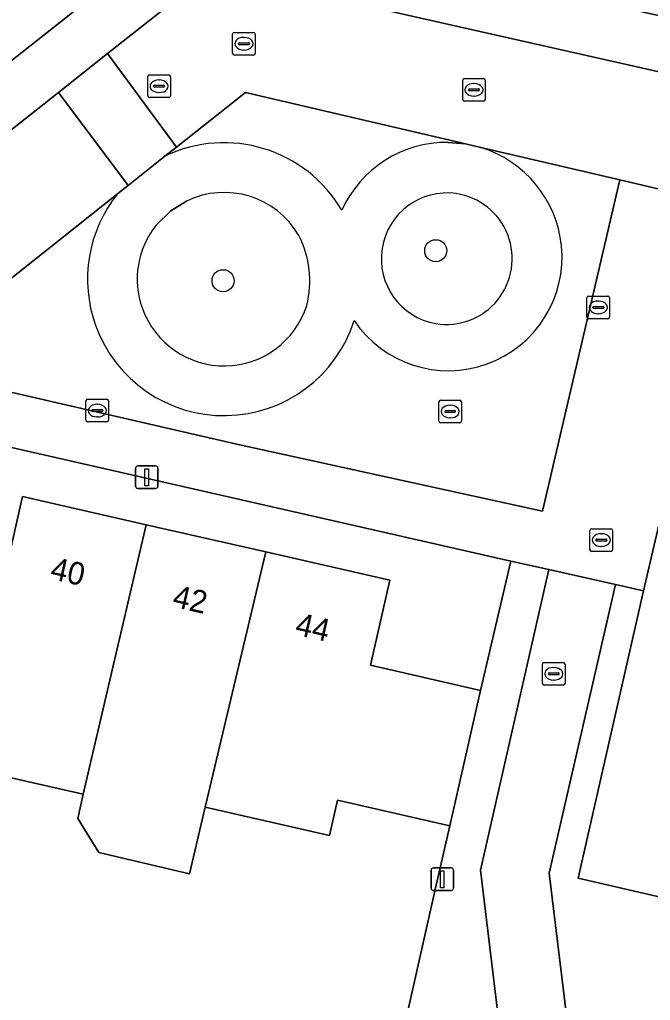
# Model space of a CAD drawing. Extents: x 159626 to 160723, y 388173 to 389416.
# Drawn here: x 160184.07 to 160211.96, y 388620.71 to 388664.1 of the extents above; entities that cross this region are included whole.
import ezdxf

# ---------------------------------------------------------------- set-up
doc = ezdxf.new("R2010")
doc.units = 0
for name, color, linetype in [('IMGEO_Boom', 7, 'Continuous'), ('IMGEO_Erf', 7, 'Continuous'), ('IMGEO_Groenvoorziening', 7, 'Continuous'), ('IMGEO_Kolk', 7, 'Continuous'), ('IMGEO_Lichtmast', 7, 'Continuous'), ('IMGEO_Muur', 7, 'Continuous'), ('IMGEO_Pand', 7, 'Continuous'), ('IMGEO_Pand_nummerreeks', 7, 'Continuous'), ('IMGEO_Rijbaan_lokaal_open', 7, 'Continuous'), ('IMGEO_Rioolput', 7, 'Continuous'), ('IMGEO_Voetpad_open', 7, 'Continuous')]:
    doc.layers.add(name, color=color, linetype=linetype)

msp = doc.modelspace()

# ---------------------------------------------------------------- linework, layer by layer
at = {"layer": 'IMGEO_Boom'}
for centre in [(160202.473, 388653.872), (160193.068, 388652.544)]:
    msp.add_circle(centre, 0.489, dxfattribs=at)
at = {"layer": 'IMGEO_Erf'}
for points in [[(160129.548, 388619.513), (160148.891, 388634.816), (160151.458, 388636.871), (160173.259, 388654.04), (160191.992, 388668.837), (160209.49, 388664.912), (160214.412, 388663.806), (160216.868, 388674.586), (160223.367, 388703.114)], [(160306.653, 388632.407), (160279.35, 388638.697), (160215.058, 388653.423), (160211.658, 388638.822), (160208.772, 388626.116), (160214.517, 388624.788), (160228.678, 388621.514), (160230.042, 388627.517), (160233.186, 388626.802), (160236.262, 388626.104), (160240.177, 388625.214), (160239.503, 388622.316), (160241.847, 388621.771), (160241.13, 388618.685)], [(160183.217, 388638.676), (160184.197, 388642.995), (160189.672, 388641.749), (160194.954, 388640.547), (160200.446, 388639.297), (160199.578, 388635.543), (160204.449, 388634.417), (160205.792, 388640.146), (160179.424, 388646.134)], [(160203.092, 388628.438), (160198.119, 388629.567), (160197.765, 388628.007), (160192.28, 388629.252), (160191.582, 388626.303), (160187.575, 388627.251), (160186.639, 388628.758), (160186.882, 388629.828), (160181.471, 388631.056)], [(160182.93, 388618.85), (160187.218, 388613.557), (160189.07, 388615.1), (160191.07, 388612.62), (160197.39, 388617.71), (160199.266, 388617.167), (160200.816, 388618.41), (160202.45, 388625.61), (160203.092, 388628.438)]]:
    msp.add_lwpolyline(points, dxfattribs=at)
at = {"layer": 'IMGEO_Groenvoorziening'}
for points in [[(160204.458, 388658.44), (160203.78, 388658.598), (160203.02, 388658.663)], [(160190.491, 388658.053), (160188.864, 388656.76), (160188.397, 388656.388)], [(160190.112, 388655.01), (160190.749, 388655.637), (160191.445, 388656.071)], [(160191.445, 388656.071), (160190.749, 388655.637), (160190.112, 388655.01)]]:
    msp.add_lwpolyline(points, dxfattribs=at)
for centre, radius, start, end in [((160193.107, 388652.616), 6.034, 30.3106, 115.694), ((160202.963, 388653.566), 5.098, 89.3598, 155.7306), ((160202.96, 388653.568), 5.097, 5.9014, 72.9066), ((160193.086, 388652.619), 6.016, 141.2048, 199.8162), ((160193.107, 388652.614), 3.835, 30.3293, 115.6727), ((160193.107, 388652.614), 3.835, 30.3293, 115.6727), ((160202.978, 388653.517), 2.914, 82.0671, 260.1206), ((160202.978, 388653.517), 2.914, 82.0671, 260.1206), ((160202.94, 388653.523), 2.913, 260.8691, 81.3185), ((160202.94, 388653.523), 2.913, 260.8691, 81.3185), ((160193.087, 388652.618), 3.818, 141.2063, 199.864), ((160193.087, 388652.618), 3.818, 141.2063, 199.864), ((160192.463, 388652.532), 4.439, 345.8967, 27.0554), ((160192.463, 388652.532), 4.439, 345.8967, 27.0554), ((160203.032, 388653.587), 5.023, 213.9515, 5.7746), ((160193.111, 388652.617), 3.839, 199.7252, 342.3074), ((160193.111, 388652.617), 3.839, 199.7252, 342.3074), ((160193.111, 388652.616), 6.039, 199.7158, 342.3075)]:
    msp.add_arc(centre, radius, start, end, dxfattribs=at)
at = {"layer": 'IMGEO_Kolk'}
for p, q in [((160189.735, 388660.724), (160189.735, 388661.576)), ((160189.81, 388661.65), (160190.662, 388661.65)), ((160190.736, 388661.576), (160190.736, 388660.724)), ((160189.994, 388661.144), (160189.994, 388661.156)), ((160190.432, 388661.107), (160190.034, 388661.107)), ((160190.037, 388661.193), (160190.435, 388661.193)), ((160190.223, 388661.43), (160190.248, 388661.43)), ((160190.478, 388661.156), (160190.478, 388661.144)), ((160203.661, 388660.565), (160203.661, 388661.417)), ((160203.736, 388661.491), (160204.588, 388661.491)), ((160204.149, 388661.271), (160204.174, 388661.271)), ((160204.662, 388661.417), (160204.662, 388660.565)), ((160190.246, 388660.87), (160190.221, 388660.87)), ((160203.92, 388660.985), (160203.92, 388660.997)), ((160204.358, 388660.948), (160203.96, 388660.948)), ((160203.963, 388661.034), (160204.361, 388661.034)), ((160204.172, 388660.711), (160204.147, 388660.711)), ((160204.404, 388660.997), (160204.404, 388660.985)), ((160190.662, 388660.65), (160189.81, 388660.65)), ((160204.588, 388660.491), (160203.736, 388660.491)), ((160209.158, 388650.938), (160209.158, 388651.79)), ((160209.233, 388651.864), (160210.085, 388651.864)), ((160209.646, 388651.644), (160209.671, 388651.644)), ((160210.159, 388651.79), (160210.159, 388650.938)), ((160209.417, 388651.358), (160209.417, 388651.37)), ((160209.855, 388651.321), (160209.457, 388651.321)), ((160209.46, 388651.407), (160209.858, 388651.407)), ((160209.901, 388651.37), (160209.901, 388651.358)), ((160210.085, 388650.864), (160209.233, 388650.864)), ((160209.669, 388651.084), (160209.644, 388651.084)), ((160187.002, 388646.376), (160187.002, 388647.228)), ((160187.077, 388647.302), (160187.929, 388647.302)), ((160188.003, 388647.228), (160188.003, 388646.376)), ((160202.682, 388647.259), (160203.534, 388647.259)), ((160187.261, 388646.796), (160187.261, 388646.808)), ((160187.304, 388646.845), (160187.702, 388646.845)), ((160187.49, 388647.082), (160187.515, 388647.082)), ((160187.745, 388646.808), (160187.745, 388646.796)), ((160202.607, 388646.333), (160202.607, 388647.185)), ((160202.909, 388646.802), (160203.307, 388646.802)), ((160203.095, 388647.039), (160203.12, 388647.039)), ((160203.608, 388647.185), (160203.608, 388646.333)), ((160187.699, 388646.759), (160187.301, 388646.759)), ((160187.513, 388646.522), (160187.488, 388646.522)), ((160202.866, 388646.753), (160202.866, 388646.765)), ((160203.304, 388646.716), (160202.906, 388646.716)), ((160203.118, 388646.479), (160203.093, 388646.479)), ((160203.35, 388646.765), (160203.35, 388646.753)), ((160187.929, 388646.302), (160187.077, 388646.302)), ((160203.534, 388646.259), (160202.682, 388646.259)), ((160207.19, 388634.73), (160207.19, 388635.582)), ((160207.265, 388635.656), (160208.117, 388635.656)), ((160208.191, 388635.582), (160208.191, 388634.73)), ((160207.449, 388635.15), (160207.449, 388635.162)), ((160207.887, 388635.113), (160207.489, 388635.113)), ((160207.492, 388635.199), (160207.89, 388635.199)), ((160207.678, 388635.436), (160207.703, 388635.436)), ((160207.933, 388635.162), (160207.933, 388635.15)), ((160208.117, 388634.656), (160207.265, 388634.656)), ((160207.701, 388634.876), (160207.676, 388634.876))]:
    msp.add_line(p, q, dxfattribs=at)
for points in [[(160189.735, 388660.724), (160189.735, 388661.576)], [(160189.81, 388661.65), (160190.662, 388661.65)], [(160190.736, 388661.576), (160190.736, 388660.724)], [(160203.661, 388660.565), (160203.661, 388661.417)], [(160203.736, 388661.491), (160204.588, 388661.491)], [(160204.662, 388661.417), (160204.662, 388660.565)], [(160190.662, 388660.65), (160189.81, 388660.65)], [(160204.588, 388660.491), (160203.736, 388660.491)], [(160209.158, 388650.938), (160209.158, 388651.79)], [(160209.233, 388651.864), (160210.085, 388651.864)], [(160210.159, 388651.79), (160210.159, 388650.938)], [(160210.085, 388650.864), (160209.233, 388650.864)], [(160187.002, 388646.376), (160187.002, 388647.228)], [(160187.077, 388647.302), (160187.929, 388647.302)], [(160188.003, 388647.228), (160188.003, 388646.376)], [(160202.682, 388647.259), (160203.534, 388647.259)], [(160202.607, 388646.333), (160202.607, 388647.185)], [(160203.608, 388647.185), (160203.608, 388646.333)], [(160187.929, 388646.302), (160187.077, 388646.302)], [(160203.534, 388646.259), (160202.682, 388646.259)], [(160207.19, 388634.73), (160207.19, 388635.582)], [(160207.265, 388635.656), (160208.117, 388635.656)], [(160208.191, 388635.582), (160208.191, 388634.73)], [(160208.117, 388634.656), (160207.265, 388634.656)]]:
    msp.add_lwpolyline(points, dxfattribs=at)
for centre, radius, start, end in [((160189.812, 388661.574), 0.0765, 91.552, 178.448), ((160189.812, 388661.574), 0.0765, 91.552, 178.448), ((160190.66, 388661.574), 0.0765, 1.552, 88.448), ((160190.66, 388661.574), 0.0765, 1.552, 88.448), ((160190.034, 388661.153), 0.0403, 85.8775, 175.7526), ((160190.031, 388661.143), 0.0366, 178.938, 274.7102), ((160190.435, 388661.15), 0.043, 264.8664, 352.4533), ((160190.439, 388661.155), 0.0386, 1.7309, 96.639), ((160203.738, 388661.415), 0.0765, 91.552, 178.448), ((160203.738, 388661.415), 0.0765, 91.552, 178.448), ((160204.586, 388661.415), 0.0765, 1.552, 88.448), ((160204.586, 388661.415), 0.0765, 1.552, 88.448), ((160189.812, 388660.726), 0.0765, 181.552, 268.448), ((160189.812, 388660.726), 0.0765, 181.552, 268.448), ((160190.66, 388660.726), 0.0765, 271.552, 358.448), ((160190.66, 388660.726), 0.0765, 271.552, 358.448), ((160203.96, 388660.994), 0.0403, 85.8775, 175.7526), ((160203.957, 388660.984), 0.0366, 178.938, 274.7102), ((160204.361, 388660.991), 0.043, 264.8664, 352.4533), ((160204.365, 388660.996), 0.0386, 1.7309, 96.639), ((160203.738, 388660.567), 0.0765, 181.552, 268.448), ((160203.738, 388660.567), 0.0765, 181.552, 268.448), ((160204.586, 388660.567), 0.0765, 271.552, 358.448), ((160204.586, 388660.567), 0.0765, 271.552, 358.448), ((160209.235, 388651.788), 0.0765, 91.552, 178.448), ((160209.235, 388651.788), 0.0765, 91.552, 178.448), ((160210.083, 388651.788), 0.0765, 1.552, 88.448), ((160210.083, 388651.788), 0.0765, 1.552, 88.448), ((160209.457, 388651.367), 0.0403, 85.8775, 175.7526), ((160209.454, 388651.357), 0.0366, 178.938, 274.7102), ((160209.858, 388651.364), 0.043, 264.8664, 352.4533), ((160209.862, 388651.369), 0.0386, 1.7309, 96.639), ((160209.235, 388650.94), 0.0765, 181.552, 268.448), ((160209.235, 388650.94), 0.0765, 181.552, 268.448), ((160210.083, 388650.94), 0.0765, 271.552, 358.448), ((160210.083, 388650.94), 0.0765, 271.552, 358.448), ((160187.079, 388647.226), 0.0765, 91.552, 178.448), ((160187.079, 388647.226), 0.0765, 91.552, 178.448), ((160187.927, 388647.226), 0.0765, 1.552, 88.448), ((160187.927, 388647.226), 0.0765, 1.552, 88.448), ((160202.684, 388647.183), 0.0765, 91.552, 178.448), ((160202.684, 388647.183), 0.0765, 91.552, 178.448), ((160203.532, 388647.183), 0.0765, 1.552, 88.448), ((160203.532, 388647.183), 0.0765, 1.552, 88.448), ((160187.301, 388646.805), 0.0403, 85.8775, 175.7526), ((160187.298, 388646.795), 0.0366, 178.938, 274.7102), ((160187.702, 388646.802), 0.043, 264.8664, 352.4533), ((160187.706, 388646.807), 0.0386, 1.7309, 96.639), ((160202.906, 388646.762), 0.0403, 85.8775, 175.7526), ((160203.311, 388646.764), 0.0386, 1.7309, 96.639), ((160187.079, 388646.378), 0.0765, 181.552, 268.448), ((160187.079, 388646.378), 0.0765, 181.552, 268.448), ((160187.927, 388646.378), 0.0765, 271.552, 358.448), ((160187.927, 388646.378), 0.0765, 271.552, 358.448), ((160202.903, 388646.752), 0.0366, 178.938, 274.7102), ((160203.307, 388646.759), 0.043, 264.8664, 352.4533), ((160202.684, 388646.335), 0.0765, 181.552, 268.448), ((160202.684, 388646.335), 0.0765, 181.552, 268.448), ((160203.532, 388646.335), 0.0765, 271.552, 358.448), ((160203.532, 388646.335), 0.0765, 271.552, 358.448), ((160207.267, 388635.58), 0.0765, 91.552, 178.448), ((160207.267, 388635.58), 0.0765, 91.552, 178.448), ((160208.115, 388635.58), 0.0765, 1.552, 88.448), ((160208.115, 388635.58), 0.0765, 1.552, 88.448), ((160207.489, 388635.159), 0.0403, 85.8775, 175.7526), ((160207.486, 388635.149), 0.0366, 178.938, 274.7102), ((160207.89, 388635.156), 0.043, 264.8664, 352.4533), ((160207.894, 388635.161), 0.0386, 1.7309, 96.639), ((160207.267, 388634.732), 0.0765, 181.552, 268.448), ((160207.267, 388634.732), 0.0765, 181.552, 268.448), ((160208.115, 388634.732), 0.0765, 271.552, 358.448), ((160208.115, 388634.732), 0.0765, 271.552, 358.448)]:
    msp.add_arc(centre, radius, start, end, dxfattribs=at)
for centre, major_axis, ratio, start_param, end_param in [((160190.222, 388661.15), (-0.387, 0.002), 0.722429, 4.712389, 7.853982), ((160190.247, 388661.15), (-0.39, 0.002), 0.717154, 1.570796, 4.712389), ((160204.148, 388660.991), (-0.387, 0.002), 0.722429, 4.712389, 7.853982), ((160204.173, 388660.991), (-0.39, 0.002), 0.717154, 1.570796, 4.712389), ((160209.645, 388651.364), (-0.387, 0.002), 0.722429, 4.712389, 7.853982), ((160209.67, 388651.364), (-0.39, 0.002), 0.717154, 1.570796, 4.712389), ((160187.489, 388646.802), (-0.387, 0.002), 0.722429, 4.712389, 7.853982), ((160187.514, 388646.802), (-0.39, 0.002), 0.717154, 1.570796, 4.712389), ((160203.094, 388646.759), (-0.387, 0.002), 0.722429, 4.712389, 7.853982), ((160203.119, 388646.759), (-0.39, 0.002), 0.717154, 1.570796, 4.712389), ((160207.677, 388635.156), (-0.387, 0.002), 0.722429, 4.712389, 7.853982), ((160207.702, 388635.156), (-0.39, 0.002), 0.717154, 1.570796, 4.712389)]:
    msp.add_ellipse(centre, major_axis=major_axis, ratio=ratio, start_param=start_param, end_param=end_param, dxfattribs=at)
at = {"layer": 'IMGEO_Lichtmast'}
for p, q in [((160189.193, 388643.454), (160189.193, 388644.254)), ((160189.193, 388644.254), (160189.193, 388643.454)), ((160189.293, 388644.354), (160190.083, 388644.354)), ((160190.083, 388644.354), (160189.293, 388644.354)), ((160190.183, 388644.254), (160190.183, 388643.454)), ((160190.183, 388643.454), (160190.183, 388644.254)), ((160190.083, 388643.354), (160189.293, 388643.354)), ((160189.293, 388643.354), (160190.083, 388643.354)), ((160202.262, 388625.67), (160202.262, 388626.47)), ((160202.262, 388626.47), (160202.262, 388625.67)), ((160202.362, 388626.57), (160203.152, 388626.57)), ((160203.152, 388626.57), (160202.362, 388626.57)), ((160203.252, 388626.47), (160203.252, 388625.67)), ((160203.252, 388625.67), (160203.252, 388626.47)), ((160203.152, 388625.57), (160202.362, 388625.57)), ((160202.362, 388625.57), (160203.152, 388625.57))]:
    msp.add_line(p, q, dxfattribs=at)
for points in [[(160189.613, 388644.229), (160189.763, 388644.229), (160189.763, 388643.479), (160189.613, 388643.479), (160189.613, 388644.229)], [(160202.682, 388626.445), (160202.832, 388626.445), (160202.832, 388625.695), (160202.682, 388625.695), (160202.682, 388626.445)]]:
    msp.add_lwpolyline(points, dxfattribs=at)
for centre, start, end in [((160189.293, 388644.254), 90, 180), ((160189.293, 388644.254), 90, 180), ((160190.083, 388644.254), 0, 90), ((160190.083, 388644.254), 360, 90), ((160189.293, 388643.454), 180, 270), ((160189.293, 388643.454), 180, 270), ((160190.083, 388643.454), 270, 0), ((160190.083, 388643.454), 270, 0), ((160202.362, 388626.47), 90, 180), ((160202.362, 388626.47), 90, 180), ((160203.152, 388626.47), 0, 90), ((160203.152, 388626.47), 360, 90), ((160202.362, 388625.67), 180, 270), ((160202.362, 388625.67), 180, 270), ((160203.152, 388625.67), 270, 0), ((160203.152, 388625.67), 270, 0)]:
    msp.add_arc(centre, 0.1, start, end, dxfattribs=at)
at = {"layer": 'IMGEO_Muur'}
msp.add_lwpolyline([(160202.45, 388625.61), (160200.816, 388618.41), (160199.266, 388617.167)], dxfattribs=at)
at = {"layer": 'IMGEO_Pand'}
for points in [[(160189.672, 388641.749), (160184.197, 388642.995), (160183.217, 388638.676), (160180.215, 388639.358), (160177.551, 388637.247), (160181.353, 388632.374), (160181.471, 388631.056), (160186.882, 388629.828)], [(160194.954, 388640.547), (160189.672, 388641.749), (160186.882, 388629.828), (160186.639, 388628.758), (160187.575, 388627.251), (160191.582, 388626.303), (160192.28, 388629.252)], [(160192.28, 388629.252), (160197.765, 388628.007), (160198.119, 388629.567), (160203.092, 388628.438), (160204.449, 388634.417), (160199.578, 388635.543), (160200.446, 388639.297), (160194.954, 388640.547)]]:
    msp.add_lwpolyline(points, close=True, dxfattribs=at)
at = {"layer": 'IMGEO_Rijbaan_lokaal_open'}
for points in [[(160214.304, 388661.344), (160192.579, 388666.247), (160187.96, 388662.596), (160190.999, 388658.454), (160194.054, 388660.865), (160203.78, 388658.598), (160204.458, 388658.44), (160210.607, 388657.006), (160213.177, 388656.407)], [(160185.781, 388660.874), (160188.864, 388656.76), (160190.491, 388658.053), (160190.999, 388658.454), (160187.96, 388662.596)], [(160185.781, 388660.874), (160177.065, 388653.985), (160180.247, 388649.923), (160188.397, 388656.388), (160188.864, 388656.76)], [(160202.45, 388625.61), (160200.816, 388618.41), (160199.266, 388617.167), (160197.814, 388616.003), (160199.68, 388613.64), (160201.546, 388611.277), (160203.413, 388608.914), (160205.279, 388606.551), (160207.204, 388604.114), (160206.833, 388606.711), (160204.445, 388626.473), (160207.478, 388639.766), (160205.792, 388640.146), (160204.449, 388634.417), (160203.092, 388628.438)], [(160207.488, 388626.34), (160210.414, 388639.103), (160207.478, 388639.766), (160204.445, 388626.473), (160206.833, 388606.711), (160207.204, 388604.114), (160208.842, 388589.812), (160211.827, 388590.336), (160211.057, 388596.802), (160209.929, 388606.242)]]:
    msp.add_lwpolyline(points, close=True, dxfattribs=at)
msp.add_lwpolyline([(160234.898, 388620.101), (160231.822, 388620.799), (160228.678, 388621.514), (160214.517, 388624.788), (160208.772, 388626.116), (160211.658, 388638.822), (160210.414, 388639.103), (160207.488, 388626.34), (160209.929, 388606.242)], dxfattribs=at)
at = {"layer": 'IMGEO_Rioolput'}
for p, q in [((160193.489, 388662.602), (160193.489, 388663.454)), ((160193.564, 388663.528), (160194.416, 388663.528)), ((160193.977, 388663.308), (160194.002, 388663.308)), ((160194.49, 388663.454), (160194.49, 388662.602)), ((160193.748, 388663.022), (160193.748, 388663.034)), ((160194.186, 388662.985), (160193.788, 388662.985)), ((160193.791, 388663.071), (160194.189, 388663.071)), ((160194.232, 388663.034), (160194.232, 388663.022)), ((160194.416, 388662.528), (160193.564, 388662.528)), ((160194, 388662.748), (160193.975, 388662.748)), ((160209.289, 388640.648), (160209.289, 388641.5)), ((160209.364, 388641.574), (160210.216, 388641.574)), ((160209.777, 388641.354), (160209.802, 388641.354)), ((160210.29, 388641.5), (160210.29, 388640.648)), ((160209.548, 388641.068), (160209.548, 388641.08)), ((160209.986, 388641.031), (160209.588, 388641.031)), ((160209.591, 388641.117), (160209.989, 388641.117)), ((160209.8, 388640.794), (160209.775, 388640.794)), ((160210.032, 388641.08), (160210.032, 388641.068)), ((160210.216, 388640.574), (160209.364, 388640.574))]:
    msp.add_line(p, q, dxfattribs=at)
for points in [[(160193.489, 388662.602), (160193.489, 388663.454)], [(160193.564, 388663.528), (160194.416, 388663.528)], [(160194.49, 388663.454), (160194.49, 388662.602)], [(160194.416, 388662.528), (160193.564, 388662.528)], [(160209.289, 388640.648), (160209.289, 388641.5)], [(160209.364, 388641.574), (160210.216, 388641.574)], [(160210.29, 388641.5), (160210.29, 388640.648)], [(160210.216, 388640.574), (160209.364, 388640.574)]]:
    msp.add_lwpolyline(points, dxfattribs=at)
for centre, radius, start, end in [((160193.566, 388663.452), 0.0765, 91.552, 178.448), ((160193.566, 388663.452), 0.0765, 91.552, 178.448), ((160194.414, 388663.452), 0.0765, 1.552, 88.448), ((160194.414, 388663.452), 0.0765, 1.552, 88.448), ((160193.788, 388663.031), 0.0403, 85.8775, 175.7526), ((160193.785, 388663.021), 0.0366, 178.938, 274.7102), ((160194.189, 388663.028), 0.043, 264.8664, 352.4533), ((160194.193, 388663.033), 0.0386, 1.7309, 96.639), ((160193.566, 388662.604), 0.0765, 181.552, 268.448), ((160193.566, 388662.604), 0.0765, 181.552, 268.448), ((160194.414, 388662.604), 0.0765, 271.552, 358.448), ((160194.414, 388662.604), 0.0765, 271.552, 358.448), ((160209.366, 388641.498), 0.0765, 91.552, 178.448), ((160209.366, 388641.498), 0.0765, 91.552, 178.448), ((160210.214, 388641.498), 0.0765, 1.552, 88.448), ((160210.214, 388641.498), 0.0765, 1.552, 88.448), ((160209.588, 388641.077), 0.0403, 85.8775, 175.7526), ((160209.585, 388641.067), 0.0366, 178.938, 274.7102), ((160209.989, 388641.074), 0.043, 264.8664, 352.4533), ((160209.993, 388641.079), 0.0386, 1.7309, 96.639), ((160209.366, 388640.65), 0.0765, 181.552, 268.448), ((160209.366, 388640.65), 0.0765, 181.552, 268.448), ((160210.214, 388640.65), 0.0765, 271.552, 358.448), ((160210.214, 388640.65), 0.0765, 271.552, 358.448)]:
    msp.add_arc(centre, radius, start, end, dxfattribs=at)
for centre, major_axis, ratio, start_param, end_param in [((160193.976, 388663.028), (-0.387, 0.002), 0.722429, 4.712389, 7.853982), ((160194.001, 388663.028), (-0.39, 0.002), 0.717154, 1.570796, 4.712389), ((160209.776, 388641.074), (-0.387, 0.002), 0.722429, 4.712389, 7.853982), ((160209.801, 388641.074), (-0.39, 0.002), 0.717154, 1.570796, 4.712389)]:
    msp.add_ellipse(centre, major_axis=major_axis, ratio=ratio, start_param=start_param, end_param=end_param, dxfattribs=at)
at = {"layer": 'IMGEO_Voetpad_open'}
for points in [[(160217.738, 388663.033), (160217.052, 388663.19), (160214.412, 388663.806), (160209.49, 388664.912), (160191.992, 388668.837), (160173.259, 388654.04), (160174.736, 388652.146), (160177.065, 388653.985), (160185.781, 388660.874), (160187.96, 388662.596), (160192.579, 388666.247), (160214.304, 388661.344), (160216.735, 388660.774), (160217.178, 388660.673)], [(160215.058, 388653.423), (160215.603, 388655.753), (160213.177, 388656.407), (160210.607, 388657.006), (160207.191, 388642.357), (160193.729, 388645.303), (160181.423, 388648.135), (160180.093, 388649.801), (160177.907, 388648.074), (160179.424, 388646.134), (160205.792, 388640.146), (160207.478, 388639.766), (160210.414, 388639.103), (160211.658, 388638.822)]]:
    msp.add_lwpolyline(points, close=True, dxfattribs=at)
for points in [[(160203.02, 388658.663), (160203.78, 388658.598), (160194.054, 388660.865), (160190.999, 388658.454), (160190.491, 388658.053)], [(160188.397, 388656.388), (160180.247, 388649.923), (160180.093, 388649.801), (160181.423, 388648.135), (160193.729, 388645.303), (160207.191, 388642.357), (160210.607, 388657.006), (160204.458, 388658.44)]]:
    msp.add_lwpolyline(points, dxfattribs=at)
for centre, radius, start, end in [((160193.107, 388652.616), 6.034, 30.3106, 115.694), ((160202.963, 388653.566), 5.098, 89.3598, 155.7306), ((160202.96, 388653.568), 5.097, 5.9014, 72.9066), ((160193.086, 388652.619), 6.016, 141.2048, 199.8162), ((160203.032, 388653.587), 5.023, 213.9515, 5.7746), ((160193.111, 388652.616), 6.039, 199.7158, 342.3075)]:
    msp.add_arc(centre, radius, start, end, dxfattribs=at)

# ---------------------------------------------------------------- texts
at = {"layer": 'IMGEO_Pand_nummerreeks'}
for s, rotation, p in [('40', 347.1772, (160185.374, 388639.363)), ('42', 347.1772, (160190.784, 388638.131)), ('44', 347.1788, (160196.204, 388636.899))]:
    msp.add_text(s, height=1, rotation=rotation, dxfattribs=at).set_placement(p)

doc.saveas('drawing.dxf')
